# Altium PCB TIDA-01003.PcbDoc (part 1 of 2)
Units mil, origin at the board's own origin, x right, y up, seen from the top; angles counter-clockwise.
Board outline 1055.12 x 1877.5 mil, 6 copper layers (Layer 1 - Top Layer, Layer 2 - GND, Layer 3 - Signal, Layer 4 - Power, Layer 5 - GND, Layer 6 - Bottom Layer), stack 66.271 mil thick; 84 components, 50 nets, 343 pads, 124 vias.
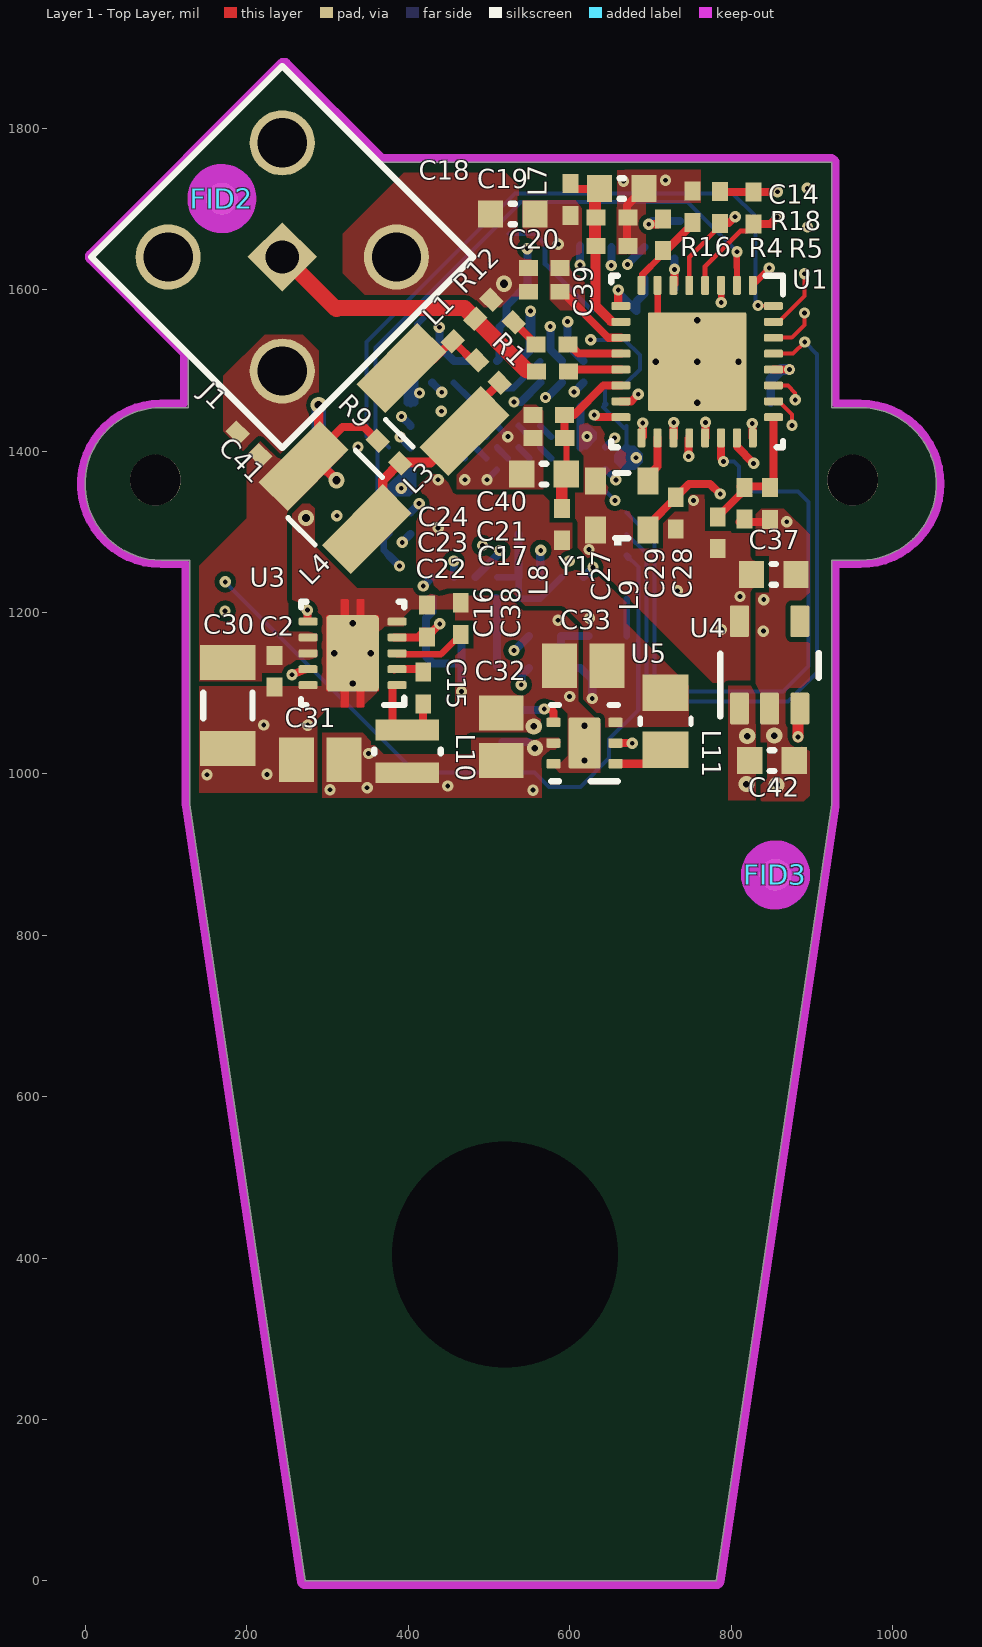
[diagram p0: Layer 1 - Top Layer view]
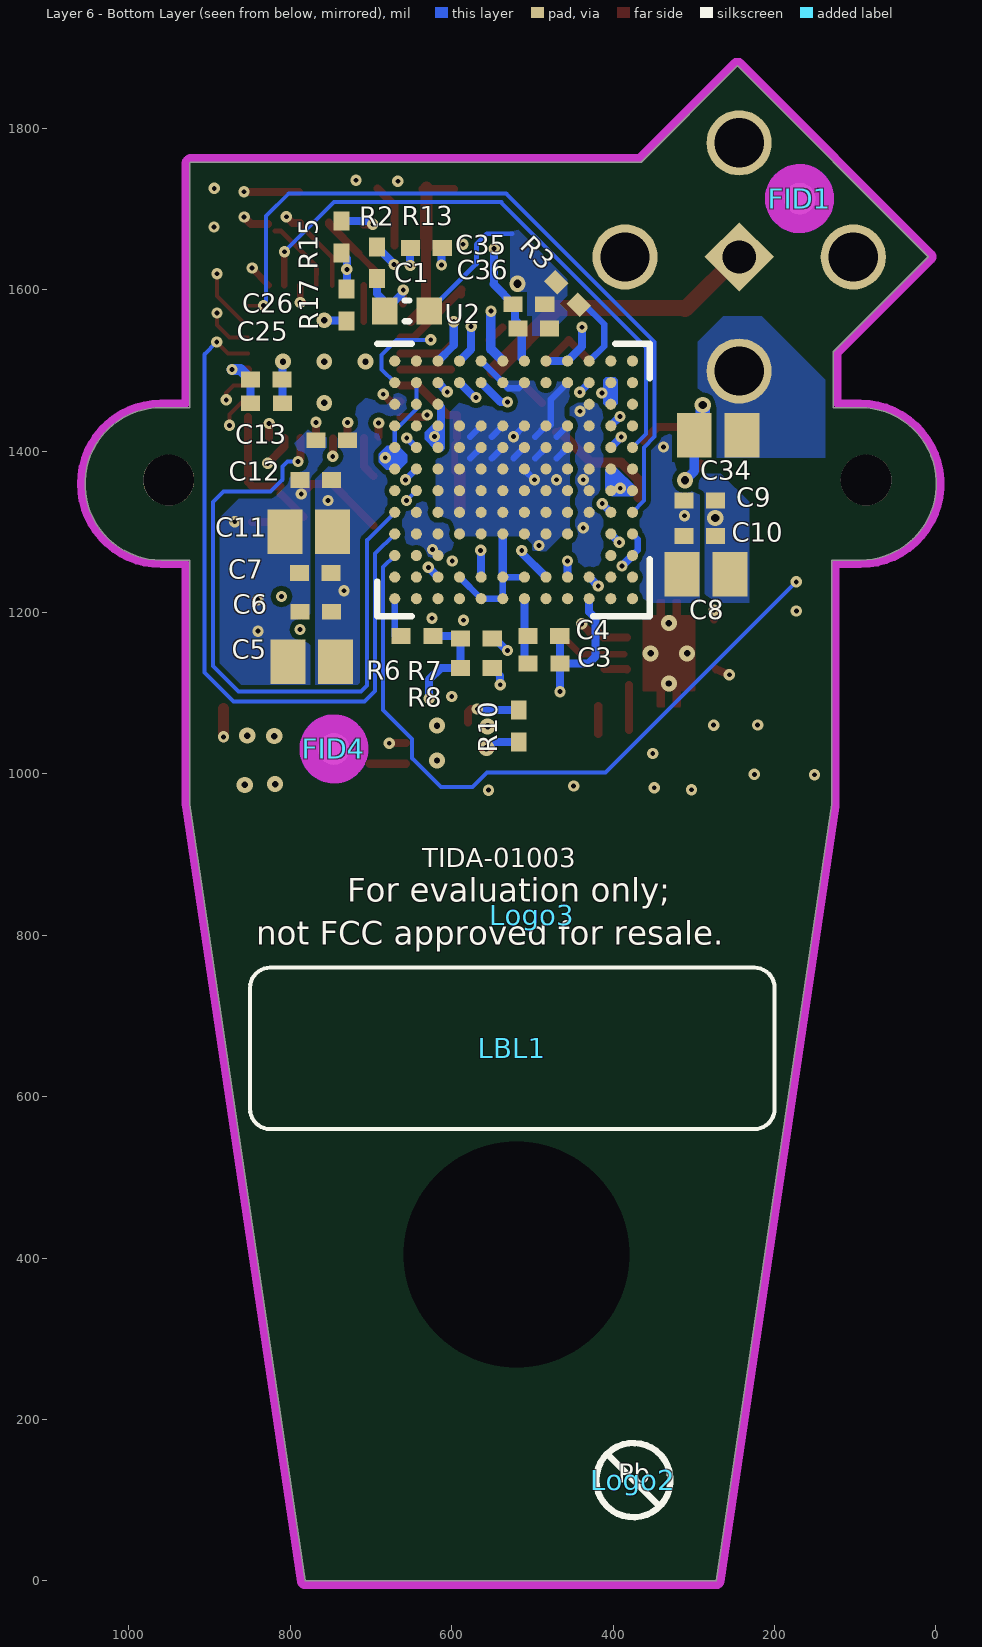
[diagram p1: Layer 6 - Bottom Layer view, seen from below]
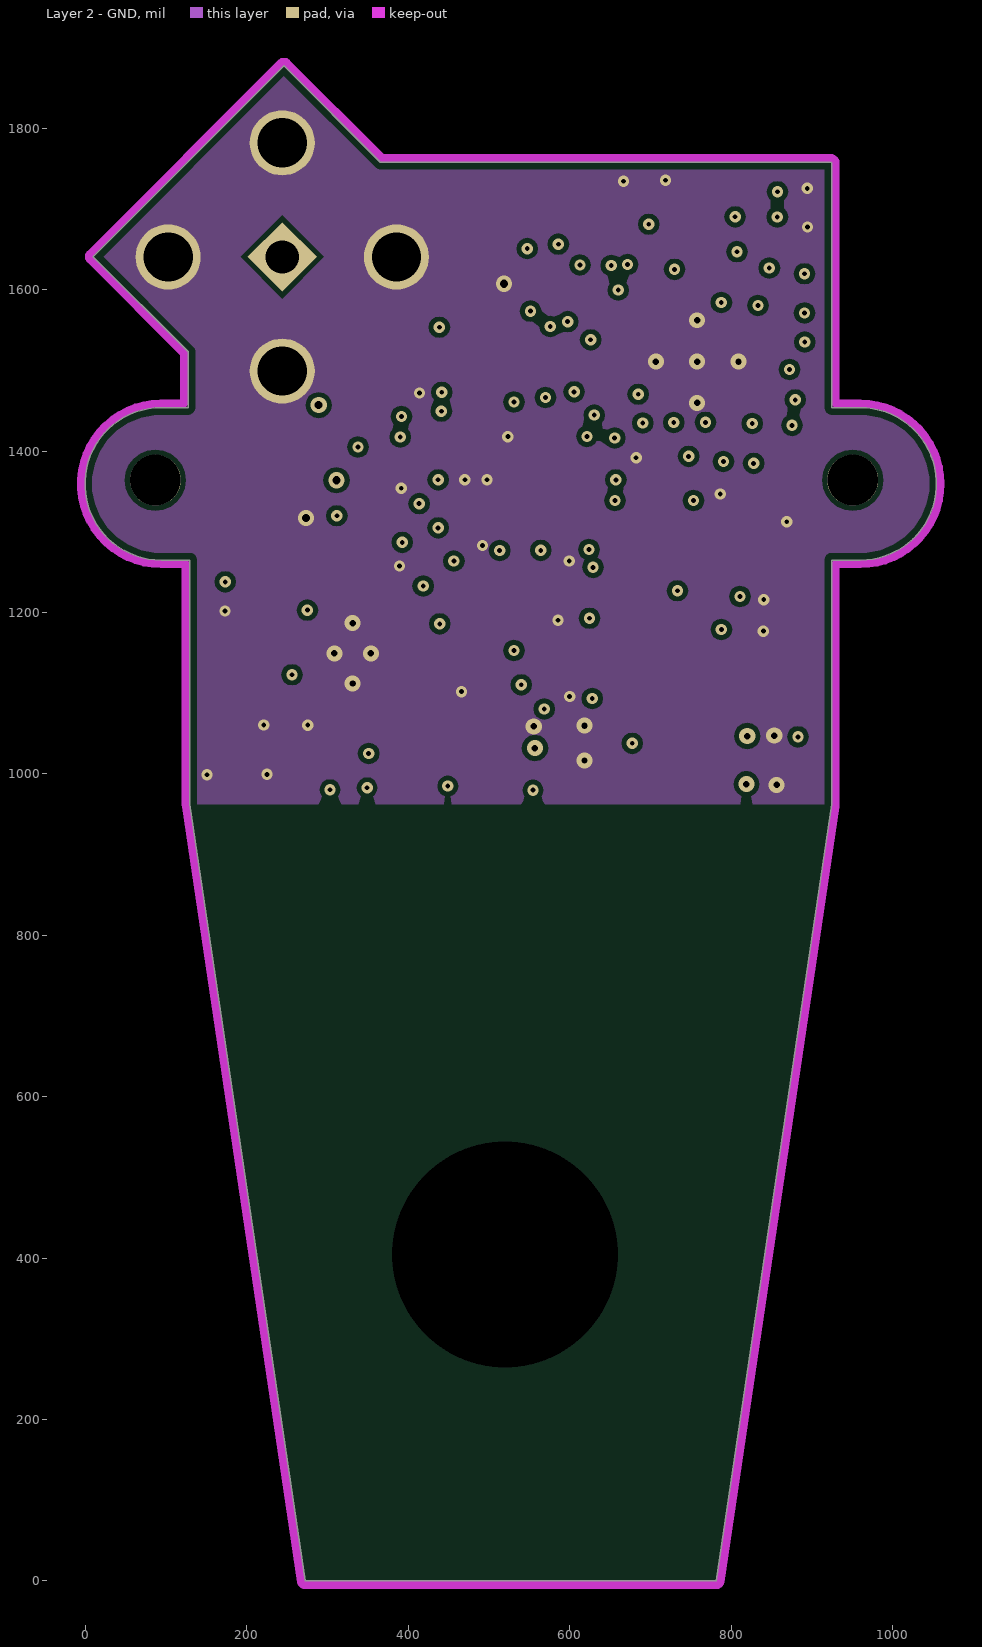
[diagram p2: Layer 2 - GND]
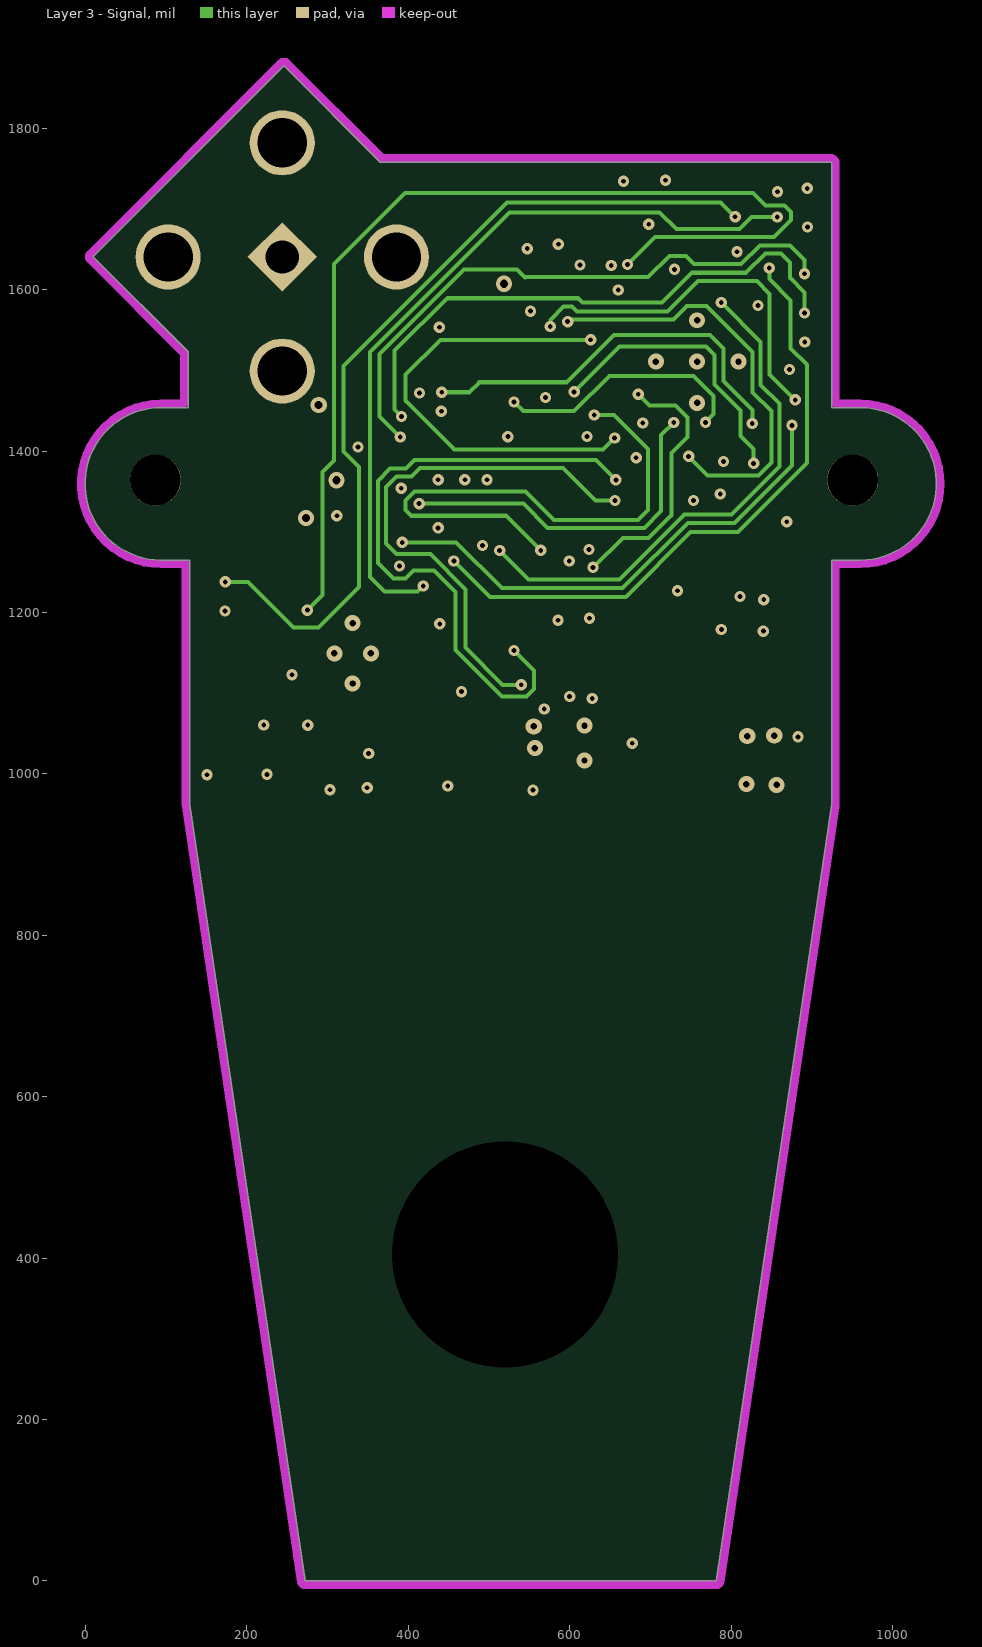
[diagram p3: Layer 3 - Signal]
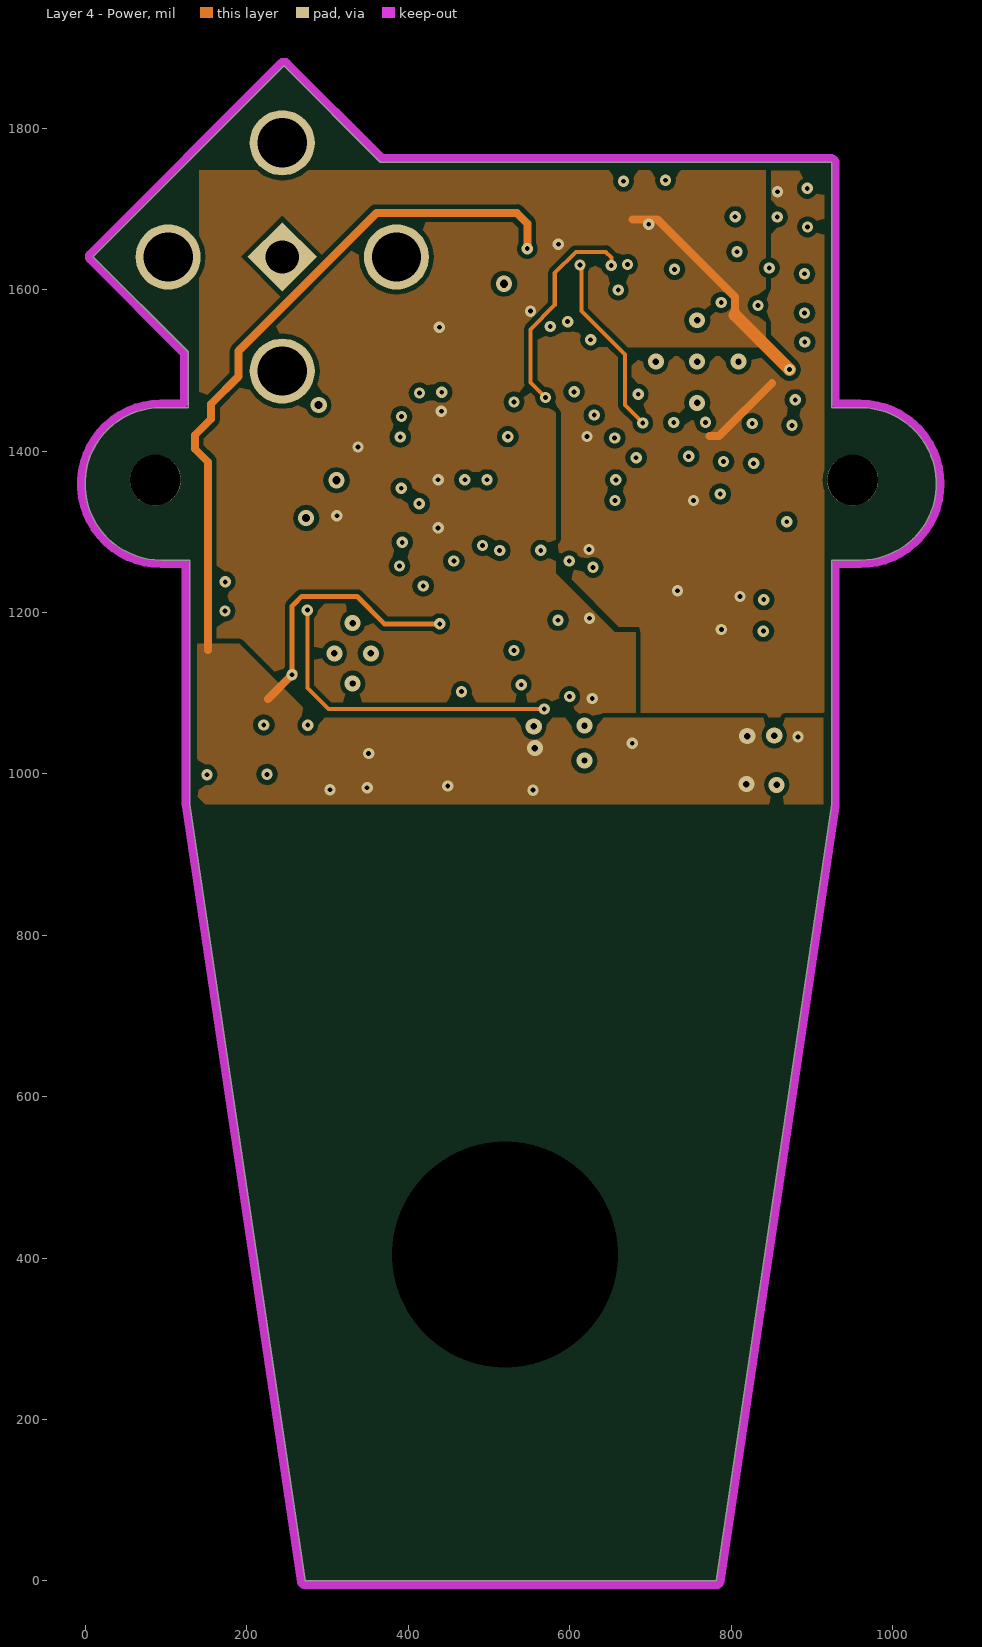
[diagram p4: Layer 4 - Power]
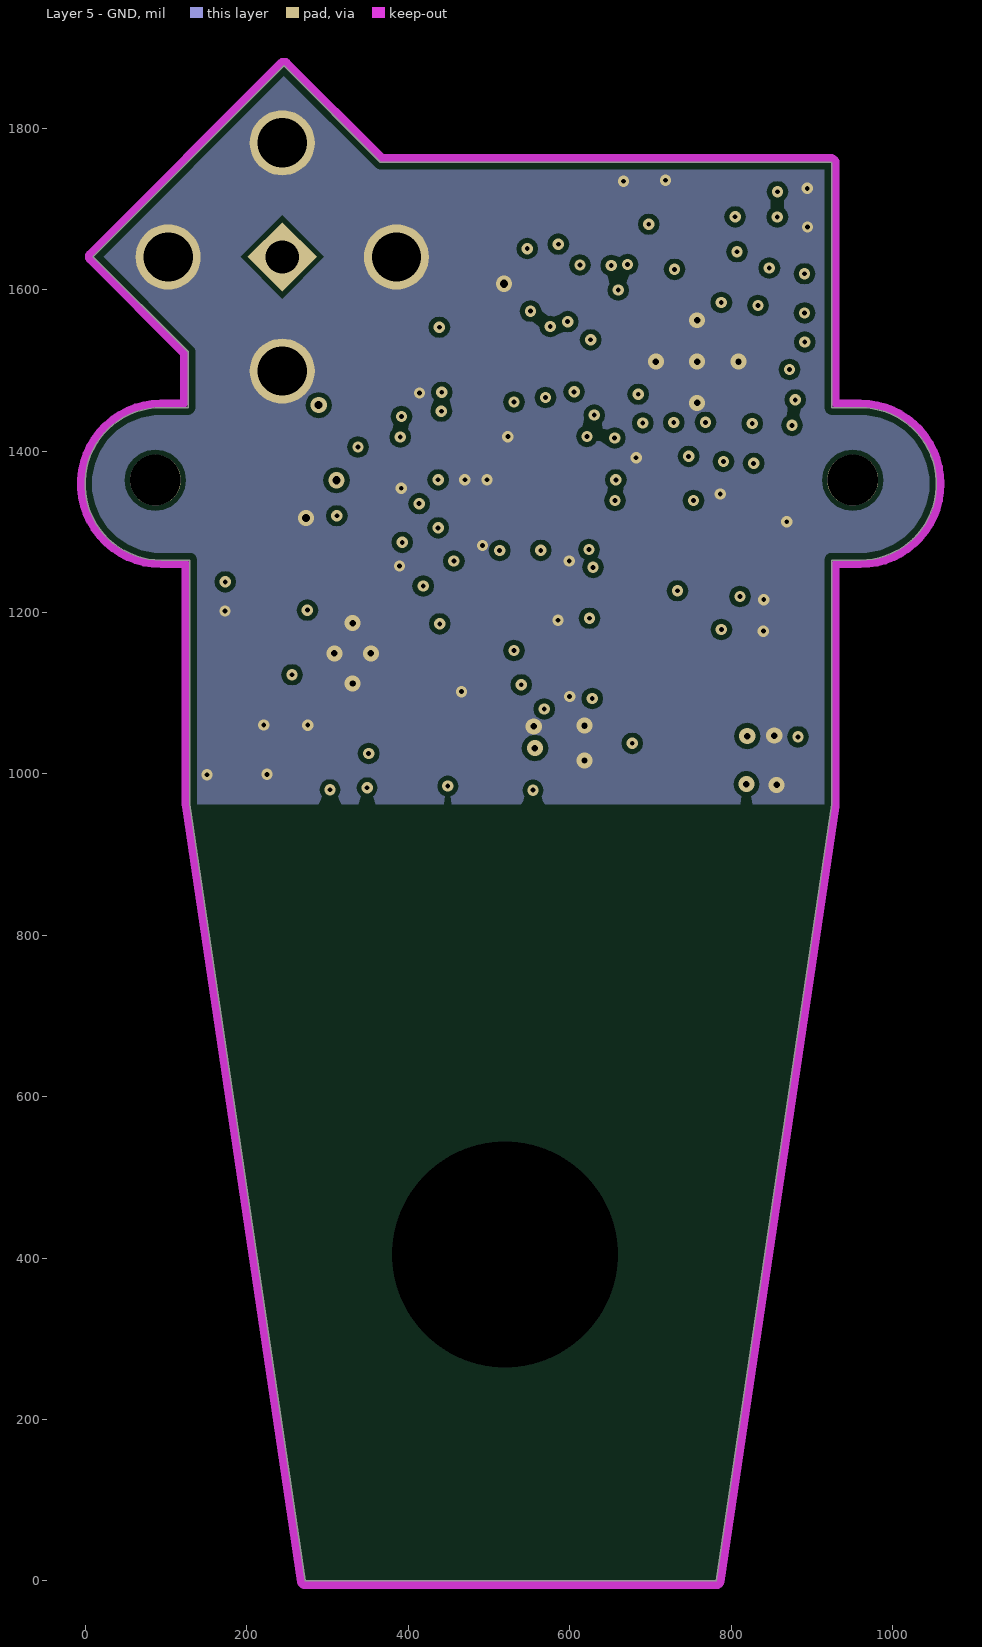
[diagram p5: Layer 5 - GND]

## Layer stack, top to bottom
Top Solder: solder mask 0.4, Solder Resist, Dk 3.5
Layer 1 - Top Layer: signal copper 1.4
Dielectric 1: core 12.6, 370HR, Dk 4.2
Layer 2 - GND: signal copper 1.417
Dielectric 2: prepreg 8, 370HR, Dk 4.2
Layer 3 - Signal: signal copper 1.417
Dielectric 3: core 16.6, 370HR, Dk 4.2
Layer 4 - Power: signal copper 1.417
Dielectric 4: prepreg 8, 370HR, Dk 4.2
Layer 5 - GND: signal copper 1.42
Dielectric 5: core 12.6, 370HR, Dk 4.2
Layer 6 - Bottom Layer: signal copper 1.4
Bottom Solder: solder mask 0.4, Solder Resist, Dk 3.5

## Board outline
93.88,1265.01 129.31,1265.01 129.31,961.86 129.31,962.5 272.2,0 781.7,0 924.59,962.5 924.59,961.86 924.59,1265.01 960.02,1265.01 ccw(c960.02,1359.5) 960.02,1453.99 924.59,1453.99 924.59,1757.14 923.6,1758.13 365.32,1758.13 245.95,1877.5 9.45,1641 127.32,1523.13 127.32,1453.99 93.88,1453.99 ccw(c93.88,1359.5)

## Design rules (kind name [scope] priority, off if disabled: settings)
AcuteAngle [All] p1: minimum=4.50000000000000E+0001 checktracksonly=FALSE
AssemblyTestPointUsage [All] p1: valid=2
BoardOutlineClearance BoardOutlineClearance_MountingHoles [OnCopper and InComponentClass('Mounting Holes')] p1: gap=40 ignorepadtopadclearanceinfootprint=FALSE
BoardOutlineClearance BoardOutlineClearance_Poly [OnCopper and InPoly] p2: gap=9 ignorepadtopadclearanceinfootprint=FALSE except(8.9: Arc-OutlineEdge Track-OutlineEdge SMDPad-OutlineEdge THPad-OutlineEdge Via-OutlineEdge Fill-OutlineEdge Poly-OutlineEdge Region-OutlineEdge Text-OutlineEdge)
BoardOutlineClearance [OnCopper and Not InComponentClass('Logo') and not InComponentClass('FiducialMark') and not InRegion(1000,500,4000,800)] p3: gap=9 ignorepadtopadclearanceinfootprint=FALSE
Clearance Clearance_fids [isarc or ispad vs iskeepout and HasFootprint('Fiducial10-20')] p1: gap=0 ignorepadtopadclearanceinfootprint=FALSE
Clearance Clearance_Keepouts [((IsTrack Or IsArc) And Not InPoly) And IsFree and IsKeepOut vs ((IsTrack Or IsArc) And Not InPoly) And IsFree and IsKeepOut] p2: gap=0 ignorepadtopadclearanceinfootprint=FALSE
Clearance Clearance_Poly [InPolygon] p3: gap=6 ignorepadtopadclearanceinfootprint=FALSE except(0: Arc-Hole Track-Hole SMDPad-Hole THPad-Hole Via-Hole Fill-Hole Poly-Hole Region-Hole Text-Hole)
Clearance [All] p4: gap=5 ignorepadtopadclearanceinfootprint=FALSE except(0: Arc-Hole Track-Hole SMDPad-Hole THPad-Hole Via-Hole Fill-Hole Poly-Hole Region-Hole Text-Hole)
ComponentClearance ComponentClearance_MountingHoles_FiducialMarks [InComponentClass('Mounting Holes') vs InComponentClass('FiducialMark')] p1: gap=5 collisioncheckmode=3 verticalgap=10 showdistances=FALSE
ComponentClearance ComponentClearance_J1_SHUNT1 [InComponent('J1') vs InComponent('FID2')] p2: gap=0 collisioncheckmode=3 verticalgap=0 showdistances=FALSE
ComponentClearance ComponentClearance_Logo [InComponentClass('Logo')] p3: gap=5 collisioncheckmode=3 verticalgap=5 showdistances=FALSE
ComponentClearance ComponentClearance_ScrewToNut [(HasFootprint('NY PMS 440 0025 PH')) vs (HasFootprint('Keystone_1902C'))] p4: gap=5 collisioncheckmode=3 verticalgap=10 showdistances=FALSE
ComponentClearance ComponentClearance_MountingHoles [InComponentClass('Mounting Holes')] p5: gap=5 collisioncheckmode=3 verticalgap=100000 showdistances=FALSE
ComponentClearance ComponentClearance_SmallPassives [HasFootprint('0201*') or HasFootprint('0402*') or HasFootprint('0508') or HasFootprint('0603*') or HasFootprint('0612') or HasFootprint('0805*') or HasFootprint('0815*') or HasFootprint('0830*') or HasFootprint('1206*') or HasFootprint('1210*') or HasFootprint('1808*') or HasFootprint('1812*') or HasFootprint('1825*') or HasFootprint('2010*') or HasFootprint('2220*') or HasFootprint('2225*') or HasFootprint('2512*') or HasFootprint('2728*') or HasFootprint('3518*') vs HasFootprint('0201*') or HasFootprint('0402*') or HasFootprint('0508') or HasFootprint('0603*') or HasFootprint('0612') or HasFootprint('0805*') or HasFootprint('0815*') or HasFootprint('0830*') or HasFootprint('1206*') or HasFootprint('1210*') or HasFootprint('1808*') or HasFootprint('1812*') or HasFootprint('1825*') or HasFootprint('2010*') or HasFootprint('2220*') or HasFootprint('2225*') or HasFootprint('2512*') or HasFootprint('2728*') or HasFootprint('3518*')] p6: gap=5 collisioncheckmode=3 verticalgap=10 showdistances=FALSE
ComponentClearance ComponentClearance_THtoSMT [IsThruComponent vs IsSMTComponent] p7: gap=5 collisioncheckmode=3 verticalgap=30 showdistances=FALSE
ComponentClearance ComponentClearance_THtoTH [IsThruComponent vs IsThruComponent] p8: gap=5 collisioncheckmode=3 verticalgap=30 showdistances=FALSE
ComponentClearance [All] p9: gap=5 collisioncheckmode=3 verticalgap=10 showdistances=FALSE
DiffPairsRouting [All] p1: maxlimit=100 minlimit=10 mostfreqgap=10 toplayer_minwidth=15 toplayer_maxwidth=15 toplayer_prefwidth=15 midlayer1_minwidth=15 midlayer1_maxwidth=15 midlayer1_prefwidth=15 midlayer2_minwidth=15 midlayer2_maxwidth=15 midlayer2_prefwidth=15 midlayer3_minwidth=15 midlayer3_maxwidth=15 midlayer3_prefwidth=15 midlayer4_minwidth=15 midlayer4_maxwidth=15 midlayer4_prefwidth=15 bottomlayer_minwidth=15 bottomlayer_maxwidth=15 bottomlayer_prefwidth=15 maxuncoupledlength=1000
FabricationTestPointUsage TestPointUsage [All] p1: valid=2 allowmultiple=FALSE
FabricationTestpoint Testpoint [All] p1: side=3 testpointundercomponent=TRUE minsize=40 maxsize=100 preferedsize=60 minholesize=0 maxholesize=40 preferedholesize=32 testpointgrid=1 allowsidetop=TRUE allowsidebottom=TRUE usegrid=TRUE gridtolerance=0.01
FanoutControl Fanout_LCC [IsLCC] p1: bgadir=Out bgaviamode=Centered fanoutstyle=Auto fanoutdirection=Alternating viagrid=1 // Fanout_LCC (Default Rule)
FanoutControl Fanout_BGA [IsBGA] p2: bgadir=Out bgaviamode=Centered fanoutstyle=Auto fanoutdirection=Alternating viagrid=1 // Fanout_BGA (Default Rule)
FanoutControl Fanout_Default [All] p4: bgadir=Out bgaviamode=Centered fanoutstyle=Auto fanoutdirection=Alternating viagrid=1 // Fanout_Default (Default Rule)
FanoutControl Fanout_Small [(CompPinCount < 5)] p5: bgadir=Out bgaviamode=Centered fanoutstyle=Auto fanoutdirection=OutThenIn viagrid=1 // Fanout_Small (Default Rule)
HoleSize [All] p1: absolutevalues=TRUE maxlimit=281 minlimit=6 maxpercent=80.000 minpercent=20.000
MinimumAnnularRing MinimumAnnularRing_ThermalPadVias [IsVia and InAnyComponent] p1: minimumring=5.91
MinimumAnnularRing [All] p2: minimumring=4
MinimumSolderMaskSliver MinimumSolderMaskSliver_Logo [InComponentClass('Logo') vs InComponentClass('Logo')] p1: minsoldermaskwidth=0.7
MinimumSolderMaskSliver [All] p2: minsoldermaskwidth=3
PlaneConnect [All] p1: planeconnectstyle=Relief reliefexpansion=10 reliefentries=4 reliefconductorwidth=10 reliefairgap=10
PolygonConnect [All] p1: connectstyle=Direct reliefconductorwidth=10 reliefentries=4 polygonreliefangle="90 Angle" airgapwidth=10
RoutingVias ThermalPadVias [IsVia and InAnyComponent] p1: holewidth=7.87 width=19.68 viastyle="Through Hole" minholewidth=7.87 minwidth=19.68 maxholewidth=12.99 maxwidth=23.62
RoutingVias [All] p2: holewidth=16 width=34 viastyle="Through Hole" minholewidth=6 minwidth=14 maxholewidth=40 maxwidth=65
SilkToBoardRegionClearance [Not ((IsComment or IsDesignator) And (Hide <> 'False')) and not InRegion(1000,500,4000,800)] p1:
SilkToSilkClearance SilkToSilkClearance_Pb-FreeLogo [(HasFootprint('Pb-Free_Overlay_Medium') OR HasFootprint('Pb-Free_Overlay_Small')) vs (HasFootprint('Pb-Free_Overlay_Medium') OR HasFootprint('Pb-Free_Overlay_Small'))] p1: silktosilkclearance=0
SilkToSilkClearance [All] p2: silktosilkclearance=4
SilkToSolderMaskClearance SilkToComponentPadClearance [IsPad and InAnycomponent] p1: minsilkscreentomaskgap=3 clearancetoexposedcopper=TRUE
SilkToSolderMaskClearance "Silk to Solder Mask Opening" [All] p2: minsilkscreentomaskgap=3 clearancetoexposedcopper=FALSE
SolderMaskExpansion [All] p1: expansion=1.97
Width [All] p1: maxlimit=100 minlimit=5 preferedwidth=10 minimp=50.000000 maximp=50.000000 favimp=50.000000 checkconnectedcopper=TRUE
15 further rules are at their usual default settings.

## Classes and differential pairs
component class "Wide Vin Serializer": C1 C14 C17 C18 C19 C20 C21 C22 C23 C24 C25 C26 C27 C28 C29 C39 C40 L7 L8 L9 R2 R12 R13 R15 R16 R17 R18 U1 Y1
component class "Wide Vin Power Supply and PoC Filter": C2 C15 C16 C30 C31 C32 C33 C34 C37 C38 C41 C42 J1 L1 L3 L4 L10 L11 R1 R9 R10 U3 U4 U5
component class "Wide Vin ON Semi Imager + Processor": C3 C4 C5 C6 C7 C8 C9 C10 C11 C12 C13 C35 C36 R3 R4 R5 R6 R7 R8 U2
component class TIDA-01003_EVM_Hardware: FID1 FID2 FID3 FID4 LBL1 Logo2 Logo3 ZZ1 ZZ2 ZZ3 ZZ4
component class FiducialMark: FID1 FID2 FID3 FID4
component class AssemblyNote: ZZ1 ZZ2 ZZ3 ZZ4
component class Label: LBL1

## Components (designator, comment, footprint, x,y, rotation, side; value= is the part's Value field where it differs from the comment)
C1 "C1608X7R1H474K080AC" 0603L 655.4,1573.9 r180 bottom value=0.47uF
C2 "CGA2B3X7R1H104K050BB" 0402L 234.1,1127.3 r270 top value=0.1uF
C3 "GRM155R61A105KE15D" 0402L 485.8,1136.9 r180 bottom value=1uF
C4 "GRM155R71C104KA88D" 0402L 485.9,1170.8 r180 bottom value=0.1uF
C5 "GRM21BR71A106KE51L" 0805L 773.5,1139 r0 bottom value=10uF
C6 "GCM155R71C104KA55D" 0402L 768.63,1201.06 r0 bottom value=0.1uF
C7 "GRM155R71C103KA01D" 0402L 769.1,1249.16 r0 bottom value=0.01uF
C8 "GRM21BR71A106KE51L" 0805L 285,1247.5 r180 bottom value=10uF
C9 "GCM155R71C104KA55D" 0402L 292.8,1338.7 r180 bottom value=0.1uF
C10 "GRM155R71C103KA01D" 0402L 292.8,1294.71 r180 bottom value=0.01uF
C11 "GRM21BR71A106KE51L" 0805L 777.13,1300.16 r0 bottom value=10uF
C12 "GRM155R61A105KE15D" 0402L 768.5,1364.5 r0 bottom value=1uF
C13 "GRM155R71C103KA01D" 0402L 748.7,1413.6 r0 bottom value=0.01uF
C14 "JMK107BB7475MA-T" 0603L 664.5,1725.5 r0 top value=4.7uF
C15 "GRM155R71C104KA88D" 0402L 418.5,1106.5 r270 top value=0.1uF
C16 "GRM155R71C103KA01D" 0402L 423,1189.5 r90 top value=0.01uF
C17 "CGA2B3X7R1H104K050BB" 0402L 578.66,1498.51 r0 top value=0.1uF
C18 "CL10B475KQ8NQNC" 0603L 529.5,1694 r180 top value=4.7µF
C19 "GRM155R71C104KA88D" 0402L 568.5,1627 r180 top value=0.1uF
C20 "GRM155R71C103KA01D" 0402L 568.5,1597.5 r180 top value=0.01uF
C21 "CGA2B3X7R1H473K050BB" 0402L 578,1532 r0 top value=0.047uF
C22 "CL10B475KQ8NQNC" 0603L 568,1371.5 r180 top value=4.7µF
C23 "GRM155R71C104KA88D" 0402L 574.2,1416.4 r180 top value=0.1uF
C24 "GRM155R71C103KA01D" 0402L 574,1445 r180 top value=0.01uF
C25 "GRM155R71C104KA88D" 0402L 829.5,1459.45 r180 bottom value=0.1uF
C26 "GRM155R71C103KA01D" 0402L 829.8,1488.85 r180 bottom value=0.01uF
C27 "GRM155R71C104KA88D" 0402L 731.5,1323.2 r90 top value=0.1uF
C28 "GRM155R71C104KA88D" 0402L 848,1335.2 r270 top value=0.1uF
C29 "GRM155R71C103KA01D" 0402L 816.5,1335.5 r270 top value=0.01uF
C30 "CGA5L3X5R1H106K160AB" 1206_190L 176.5,1085 r270 top value=10uF
C31 "CL21B226MQQNNNE" 0805L 291,1017.5 r180 top value=22uF
C32 "CL21B106KOQNNNE" 0805L 515.5,1046 r90 top value=10uF
C33 "GRM21BR71A106KE51L" 0805L 616.8,1134.3 r180 top value=10uF
C34 "CGA4J3X5R1H475M125AB" 0805L 270,1420 r180 bottom value=4.7uF
C35 "GRM155R61A105KE15D" 0402L 504.5,1582 r180 bottom value=1uF
C36 "C1005X7R1E104K050BB" 0402L 498.5,1552 r180 bottom value=0.1µF
C37 "LMK107B7105KAHT" 0603L 852.9,1247.41 r0 top value=1uF
C38 "GRM155R61A105KE15D" 0402L 465,1192.5 r90 top value=1uF
C39 "GRM155R71C104KA88D" 0402L 652.5,1689.4 r0 top value=0.1uF
C40 "GRM155R71C103KA01D" 0402L 652.5,1654 r0 top value=0.01uF
C41 "CGA2B3X7R1H104K050BB" 0402L 202.42,1409.08 r135 top value=0.1uF
C42 "LMK107B7105KAHT" 0603L 850.5,1016.5 r0 top value=1uF
FID1 "Fiducial" Fiducial10-20 169,1713 r180 bottom
FID2 "Fiducial" Fiducial10-20 169,1713 r0 top
FID3 "Fiducial" Fiducial10-20 855,875 r0 top
FID4 "Fiducial" Fiducial10-20 746,1031 r180 bottom
J1 "59S10H-40ML5-Z" Rosenberger_59S10H-40ML5-Z 243.88,1640.63 r225 top
L1 "BLM15AX102SN1D" 0402L 469,1550 r225 top value="1000 ohm"
L3 "CBC3225T4R7MR" CBC3225 430.5,1464 r315 top value=4.7uH
L4 "CBC3225T101MR" CBC3225 309.5,1342.5 r135 top value=100uH
L7 "BLM15AX102SN1D" 0402L 600.9,1711.9 r90 top value="1000 ohm"
L8 "BLM15AX102SN1D" 0402L 590.3,1309.3 r90 top value="1000 ohm"
L9 "BLM15AX102SN1D" 0402L 783.5,1299 r90 top value="1000 ohm"
L10 "NRV2010T4R7MGF" NRV2010 399,1028 r270 top value=4.7uH
L11 "MLZ2012M2R2HTD25" 0805_150 718.8,1065.3 r90 top value=2.2uH
LBL1 "Size: 0.65\" x 0.20 \"" Label_650x200 525,660 r0 bottom
Logo2 "Pb-Free Symbol" Pb-Free_Overlay_Small 375,125 r180 bottom
Logo3 "FCC disclaimer" FCC_disclaimer_stacked 500,825 r180 bottom
R1 "CRCW04022K00FKED" 0402L 499.5,1498.5 r135 top value=2.00k
R2 "CRCW040210K0JNED" 0402L 692.8,1633.5 r90 bottom value=10k
R3 "CRCW040210K0JNED" 0402L 456.5,1595.5 r225 bottom value=10k
R4 "CRCW04023K30JNED" 0402L 786.5,1702 r90 top value=3.3k
R5 "CRCW04023K30JNED" 0402L 827.6,1701.2 r90 top value=3.3k
R6 "CRCW040210K0JNED" 0402L 643,1171 r180 bottom value=10k
R7 "CRCW04023K30JNED" 0402L 569.5,1168 r0 bottom value=3.3k
R8 "CRCW04023K30JNED" 0402L 569.5,1131.5 r0 bottom value=3.3k
R9 "CRCW04022K00FKED" 0402L 376,1399 r315 top value=2.00k
R10 "CRCW04021K00FKED" 0402L 517,1059.5 r270 bottom value=1.00k
R12 "CRCW040249R9FKED" 0402L 517,1573.5 r135 top value=49.9
R13 "CRCW040233R0JNED" 0402L 631.5,1651.7 r0 bottom value=33
R15 "CRCW040210K0JNED" 0402L 736.6,1665.3 r90 bottom value=10k
R16 "CRCW040210K0JNED" 0402L 715.8,1668.2 r90 top value=10k
R17 "CRCW04020000Z0ED" 0402L 730.3,1581.2 r90 bottom value=0
R18 "CRG0402F4K7" 0402L 752.3,1702.8 r270 top value=4.70k
U1 "DS90UB913ATRTVTQ1" RTV0032A 758,1511 r270 top
U2 "ON Semiconductor AS0140AT" BGA130_850x850x162 523.4,1364.43 r0 bottom locked
U3 "LM53600NQDSXRQ1" DSX0010A 331,1149.5 r180 top
U4 "LP5907QMFX-2.8Q1" DBV0005A_N 847.8,1135.21 r90 top
U5 "TPS62261TDRVRQ1" DRV0006A 618.3,1038.3 r180 top
Y1 "ASDMB-48.000MHZ-LY-T" Abracon_ASDMB 664.5,1332.6 r90 top
ZZ1 "This Assembly Note is for PCB labels only" AssemblyNoteLabel 185,3938 r0 top
ZZ2 "These assemblies are ESD sensitive, ESD precautions shall be observed." AssemblyNote 185,3829.11 r0 top
ZZ3 "These assemblies must be clean and free from flux and all contaminants. Use of no clean flux is not acceptable." AssemblyNote 185,3740.56 r0 top
ZZ4 "These assemblies must comply with workmanship standards IPC-A-610 Class 2, unless otherwise specified." AssemblyNote 185,3652 r0 top

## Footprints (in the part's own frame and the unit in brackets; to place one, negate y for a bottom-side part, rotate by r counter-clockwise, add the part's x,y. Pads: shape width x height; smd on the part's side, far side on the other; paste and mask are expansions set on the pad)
0402L [mm] "0402 from SM-752 data"
  rect 0.6x0.5 smd: 1(-0.5,0) 2(0.5,0)
  body extent -0.55,-0.3 0.55,0.3, height 0.6
0603L [mm] "0603 from SM-752 data"
  rect 0.8x0.85 smd: 1(-0.7,0) 2(0.7,0)
  silkscreen extent -0.07,-0.33 0.07,0.33, body extent -0.87,-0.47 0.87,0.47, height 1
0805_150 [mm] "0805 / 1.5 mm height"
  rect 1.15x1.45 smd: 1(-0.9,0) 2(0.9,0)
  silkscreen extent -0.1,-0.8 0.1,0.8, body extent -1.1,-0.72 1.1,0.72, height 1.5
0805L [mm] "0805 from SM-752 data"
  rect 1.1x1.4 smd: 1(-0.75,0) 2(0.75,0)
  body extent -1.1,-0.72 1.1,0.72, height 1.45
1206_190L [mm] "1206_190"
  rect 1.1x1.75 smd: 1(-1.35,0) 2(1.35,0)
  silkscreen extent -0.4,-0.77 0.4,0.77, body extent -1.75,-0.95 1.75,0.95, height 1.9
Abracon_ASDMB [mm] "SMD, 4-Leads, Body 2.5x2mm"
  rect 0.85x0.65 smd: 1(-0.775,0.825) 2(-0.775,-0.825) 3(0.775,-0.825) 4(0.775,0.825)
  silkscreen extent -1.25,-0.2 1.02,0.25, body extent -1.02,-1.27 1.02,1.28, height 0.91
AssemblyNote [mil] "Assembly Note"
AssemblyNoteLabel [mil] "Assembly Note for PCB Labels"
BGA130_850x850x162 [mm] "BGA, 130-Balls, Body 8.5x8.5mmx1.62mm, Pitch 0.68mm"
  round 0.35 smd: A1(-3.74,3.74) A2(-3.06,3.74) A3(-2.38,3.74) A4(-1.7,3.74) A5(-1.02,3.74) A6(-0.34,3.74) A7(0.34,3.74) A8(1.02,3.74) A9(1.7,3.74) A10(2.38,3.74) A11(3.06,3.74) A12(3.74,3.74) B1(-3.74,3.06) B2(-3.06,3.06) B3(-2.38,3.06) B4(-1.7,3.06) B5(-1.02,3.06) B6(-0.34,3.06) B7(0.34,3.06) B8(1.02,3.06) B9(1.7,3.06) B10(2.38,3.06) B11(3.06,3.06) B12(3.74,3.06) C1(-3.74,2.38) C2(-3.06,2.38) C10(2.38,2.38) C11(3.06,2.38) C12(3.74,2.38) D1(-3.74,1.7) D2(-3.06,1.7) D4(-1.7,1.7) D5(-1.02,1.7) D6(-0.34,1.7) D7(0.34,1.7) D8(1.02,1.7) D9(1.7,1.7) D10(2.38,1.7) D11(3.06,1.7) D12(3.74,1.7) E1(-3.74,1.02) E2(-3.06,1.02) E3(-2.38,1.02) E4(-1.7,1.02) E5(-1.02,1.02) E6(-0.34,1.02) E7(0.34,1.02) E8(1.02,1.02) E9(1.7,1.02) E10(2.38,1.02) E11(3.06,1.02) E12(3.74,1.02) F1(-3.74,0.34) F2(-3.06,0.34) F3(-2.38,0.34) F4(-1.7,0.34) F5(-1.02,0.34) F6(-0.34,0.34) F7(0.34,0.34) F8(1.02,0.34) F9(1.7,0.34) F10(2.38,0.34) F11(3.06,0.34) F12(3.74,0.34) G1(-3.74,-0.34) G2(-3.06,-0.34) G3(-2.38,-0.34) G4(-1.7,-0.34) G5(-1.02,-0.34) G6(-0.34,-0.34) G7(0.34,-0.34) G8(1.02,-0.34) G9(1.7,-0.34) G10(2.38,-0.34) G11(3.06,-0.34) G12(3.74,-0.34) H1(-3.74,-1.02) H2(-3.06,-1.02) H3(-2.38,-1.02) H4(-1.7,-1.02) H5(-1.02,-1.02) H6(-0.34,-1.02) H7(0.34,-1.02) H8(1.02,-1.02) H9(1.7,-1.02) H10(2.38,-1.02) H11(3.06,-1.02) H12(3.74,-1.02) J1(-3.74,-1.7) J2(-3.06,-1.7) J3(-2.38,-1.7) J4(-1.7,-1.7) J5(-1.02,-1.7) J6(-0.34,-1.7) J7(0.34,-1.7) J8(1.02,-1.7) J9(1.7,-1.7) J10(2.38,-1.7) J11(3.06,-1.7) J12(3.74,-1.7) K1(-3.74,-2.38) K2(-3.06,-2.38) K3(-2.38,-2.38) K10(2.38,-2.38) K11(3.06,-2.38) K12(3.74,-2.38) L1(-3.74,-3.06) L2(-3.06,-3.06) L3(-2.38,-3.06) L4(-1.7,-3.06) L5(-1.02,-3.06) L6(-0.34,-3.06) L7(0.34,-3.06) L8(1.02,-3.06) L9(1.7,-3.06) L10(2.38,-3.06) L11(3.06,-3.06) L12(3.74,-3.06) M1(-3.74,-3.74) M2(-3.06,-3.74) M3(-2.38,-3.74) M4(-1.7,-3.74) M5(-1.02,-3.74) M6(-0.34,-3.74) M7(0.34,-3.74) M8(1.02,-3.74) M9(1.7,-3.74) M10(2.38,-3.74) M11(3.06,-3.74) M12(3.74,-3.74)
  silkscreen extent -4.29,-4.29 4.29,4.29, body extent -4.34,-4.34 4.34,4.34, height 1.62
CBC3225 [mm] "TAIYO YUDEN, IPC nominal footprint."
  rect 1.29x2.72 smd: 1(-1.405,0) 2(1.405,0)
  silkscreen extent -0.6,-1.5 0.6,-1.5, body extent -1.7,-1.35 1.7,1.35, height 2.7
DBV0005A_N [mm] "SOT23, 5-Leads, Body 2.9x1.6mm, Pitch 0.95mm, Lead Span 2.8mm, IPC Medium Density"
  rrect17% 1x0.6 smd: 1(-1.375,0.95) 2(-1.375,0) 3(-1.375,-0.95) 4(1.375,-0.95) 5(1.375,0.95)
  silkscreen extent -1.63,-1.55 0.38,1.55, body extent -1.42,-1.46 1.42,1.46, height 1.09
DRV0006A [mm] "SON, 6-Leads, Body 2x2mm, Pitch 0.65mm, Thermal Pad 1.6x1mm, TI Recommended"
  rrect33% 0.45x0.3 smd: 1(-0.975,0.65) 2(-0.975,0) 3(-0.975,-0.65) 4(0.975,-0.65) 5(0.975,0) 6(0.975,0.65)
  rrect14% 1x0.7 on Top Paste: 7(0,0.45) 7(0,-0.45)
  rrect10% 1x1.6 smd paste-0.5: 7(0,0)
  silkscreen extent -1.05,-1.2 1.05,1.2, body extent -1.05,-1.05 1.05,1.05, height 0.81
DSX0010A [mm] "SON, 10-Leads, Body 3x3 mm, Pitch 0.5mm"
  rrect40% 0.6x0.25 smd: 1(-1.4,1) 2(-1.4,0.5) 3(-1.4,0) 4(-1.4,-0.5) 5(-1.4,-1) 6(1.4,-1) 7(1.4,-0.5) 8(1.4,0) 9(1.4,0.5) 10(1.4,1)
  rrect40% 0.25x0.34 on Top Paste: 11(-0.25,1.53) 11(-0.25,-1.53) 11(0.25,1.53) 11(0.25,-1.53)
  rrect9% 1.5x1.06 on Top Paste: 11(0,0.63) 11(0,-0.63)
  rrect12% 1.65x2.4 smd paste-1 mask-2: 11(0,0)
  Layer 1 - Top Layer region: -0.775,-1.2 -0.375,-1.2 -0.375,-1.65 -0.371,-1.669 -0.36,-1.685 -0.344,-1.696 -0.325,-1.7 -0.325,-1.7 -0.325,-1.7 -0.175,-1.7 -0.175,-1.7 -0.156,-1.696 -0.14,-1.685 -0.129,-1.669 -0.125,-1.65 -0.125,-1.65 -0.125,-1.65 -0.125,-1.2 0.125,-1.2 0.125,-1.65 0.129,-1.669 0.14,-1.685 0.156,-1.696 0.175,-1.7 0.175,-1.7 0.175,-1.7 0.325,-1.7 0.325,-1.7 0.344,-1.696 0.36,-1.685 0.371,-1.669 0.375,-1.65 0.375,-1.65 0.375,-1.2 0.775,-1.2 0.794,-1.196 0.81,-1.185 0.821,-1.169 0.825,-1.15 0.825,-1.15 0.825,1.15 0.821,1.169 0.81,1.185 0.794,1.196 0.775,1.2 0.775,1.2 0.375,1.2 0.375,1.65 0.371,1.669 0.36,1.685 0.344,1.696 0.325,1.7 0.325,1.7 0.175,1.7 0.156,1.696 0.14,1.685 0.129,1.669 0.125,1.65 0.125,1.65 0.125,1.2 -0.125,1.2 -0.125,1.65 -0.125,1.65 -0.129,1.669 -0.14,1.685 -0.156,1.696 -0.175,1.7 -0.175,1.7 -0.325,1.7 -0.344,1.696 -0.36,1.685 -0.371,1.669 -0.375,1.65 -0.375,1.65 -0.375,1.2 -0.775,1.2 -0.794,1.196 -0.81,1.185 -0.821,1.169 -0.825,1.15 -0.825,1.15 -0.825,-1.15 -0.821,-1.169 -0.81,-1.185 -0.794,-1.196 -0.775,-1.2
  silkscreen extent -1.63,-1.63 1.63,1.63, body extent -1.5,-1.5 1.5,1.5, height 0.8
FCC_disclaimer_stacked [mil]
Fiducial10-20 [mm]
  round 1 smd mask+0.5: 1(0,0)
  Layer 1 - Top Layer keep-out circle w1.178: c0,0 r0.5
Label_650x200 [mil] "Thermal Transfer Label"
  round 1 on Mech14: 0(0,0)
  silkscreen extent -325,-100 325,100, body extent -325,-100 325,100, height 1
NRV2010 [mm] "SMD, 2-Leads, Body 2x2mm"
  rect 0.65x2 smd: 1(-0.675,0) 2(0.675,0)
  silkscreen extent -0.06,-1.05 0.06,1.05, body extent -1.05,-1.05 1.05,1.05, height 1
Pb-Free_Overlay_Small [mil]
  silkscreen extent -46,-46 46,46
Rosenberger_59S10H-40ML5-Z [mm] "Connector, HF, TH"
  rect 1.55x1.55 hole 1.05: 1(0,0)
  round 2.05 hole 1.55: 2(-2.54,2.54) 3(2.54,2.54) 4(2.54,-2.54) 5(-2.54,-2.54)
  silkscreen extent -4.25,-4.25 4.25,4.25, body extent -4.25,-5.75 4.25,4.25, height 12.45
RTV0032A [mm] "QFN, 32-Leads, Body 5x5mm, Pitch 0.5mm"
  rrect40% 0.6x0.25 smd: 1(-2.4,1.75) 2(-2.4,1.25) 3(-2.4,0.75) 4(-2.4,0.25) 5(-2.4,-0.25) 6(-2.4,-0.75) 7(-2.4,-1.25) 8(-2.4,-1.75) 17(2.4,-1.75) 18(2.4,-1.25) 19(2.4,-0.75) 20(2.4,-0.25) 21(2.4,0.25) 22(2.4,0.75) 23(2.4,1.25) 24(2.4,1.75)
  rrect40% 0.25x0.6 smd: 9(-1.75,-2.4) 10(-1.25,-2.4) 11(-0.75,-2.4) 12(-0.25,-2.4) 13(0.25,-2.4) 14(0.75,-2.4) 15(1.25,-2.4) 16(1.75,-2.4) 25(1.75,2.4) 26(1.25,2.4) 27(0.75,2.4) 28(0.25,2.4) 29(-0.25,2.4) 30(-0.75,2.4) 31(-1.25,2.4) 32(-1.75,2.4)
  rrect3% 3.1x3.1 smd paste-1.55: 33(0,0)
  silkscreen extent -2.7,-2.7 2.7,2.7, body extent -2.55,-2.55 2.55,2.55, height 0.81

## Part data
C1: "CAP, CERM, 0.47 µF, 50 V, +/- 10%, X7R, 0603", Cap_Case=0603, Manufacturer=TDK, Supplier Part Number 1=445-5952-1-ND, TempCo=X7R, Tolerance_%=10, Value1="0.010974 ohm", Value2=50V, ValueDisplayed=0.47µF
C2: "CAP, CERM, 0.1 µF, 50 V, +/- 10%, X7R, AEC-Q200 Grade 1, 0402", Cap_Case=0402, Manufacturer=TDK, Supplier Part Number 1=445-6899-1-ND, TempCo=X7R, Tolerance_%=10, Value1=Unknown, Value2=50V, ValueDisplayed=0.1µF
C3 C12 C35 C38: "CAP, CERM, 1 µF, 10 V, +/- 10%, X5R, 0402", Cap_Case=0402, Manufacturer=MuRata, Supplier Part Number 1=490-3890-1-ND, TempCo=X5R, Tolerance_%=10, Value1=Unknown, Value2=10V, ValueDisplayed=1µF
C4 C19 C23 C25 C27 C28: "CAP, CERM, 0.1uF, 16V, +/-10%, X7R, 0402", Cap_Case=0402, Manufacturer=MuRata, Supplier Part Number 1=490-3261-1-ND, TempCo=X7R, Tolerance_%=10, Value1=Unknown, Value2=16V, ValueDisplayed=0.1µF
C5 C8 C11: "CAP, CERM, 10uF, 10V, +/-10%, X7R, 0805", Cap_Case=0805, Manufacturer=MuRata, Supplier Part Number 1=490-3905-1-ND, TempCo=X7R, Tolerance_%=10, Value1="0.003 ohm", Value2=10V, ValueDisplayed=10µF
C6 C9: "CAP, CERM, 0.1 µF, 16 V, +/- 10%, X7R, 0402", Cap_Case=0402, Manufacturer=MuRata, Supplier Part Number 1=490-4759-2-ND, TempCo=X7R, Tolerance_%=10, Value1=Unknown, Value2=16V, ValueDisplayed=0.1µF
C7 C10 C13 C16 C20 C24 C26 C29 C40: "CAP, CERM, 0.01uF, 16V, +/-10%, X7R, 0402", Cap_Case=0402, Manufacturer=MuRata, Supplier Part Number 1=490-1313-1-ND, TempCo=X7R, Tolerance_%=10, Value1=Unknown, Value2=16V, ValueDisplayed=0.01µF
C14: "CAP, CERM, 4.7 µF, 6.3 V, +/- 10%, X7R, 0603", Cap_Case=0603, Manufacturer="Taiyo Yuden", TempCo=X7R, Tolerance_%=10, Value1=Unknown, Value2=6.3V, ValueDisplayed=4.7µF
C15 C39: "CAP, CERM, 0.1 µF, 16 V, +/- 10%, X7R, 0402", Cap_Case=0402, Manufacturer=MuRata, Supplier Part Number 1=490-3261-1-ND, TempCo=X7R, Tolerance_%=10, Value1=Unknown, Value2=16V, ValueDisplayed=0.1µF
C17 C41: "CAP, CERM, 0.1 µF, 50 V, +/- 10%, X7R, AEC-Q200 Grade 1, 0402", Cap_Case=0402, Manufacturer=TDK, Supplier Part Number 1=445-6899-1-ND, TempCo=X7R, Tolerance_%=10, Value1="0.039064 ohm", Value2=50V, ValueDisplayed=0.1µF
C18 C22: library part Capacitor, "CAP CER 4.7UF 6.3V 10% X7R 0603", Alternate Manufacturer=-, Manufacturer="Samsung Electro-Mechanics America, Inc", Operating Temperature="-55°C ~ 125°C", Supplier Part Number 1=1276-2087-1-ND, TempCo=X7R, Tolerance_%=±10%
C21: "CAP, CERM, 0.047 µF, 50 V, +/- 10%, X7R, AEC-Q200 Grade 1, 0402", Cap_Case=0402, Manufacturer=TDK, Supplier Part Number 1=445-6897-1-ND, TempCo=X7R, Tolerance_%=10, Value1="0.06407 ohm", Value2=50V, ValueDisplayed=0.047µF
C30: "CAP, CERM, 10 µF, 50 V, +/- 10%, X5R, 1206_190", Cap_Case=1206, Manufacturer=TDK, Supplier Part Number 1=445-7886-1-ND, TempCo=X5R, Tolerance_%=10, Value1=Unknown, Value2=50V, ValueDisplayed=10µF
C31: "CAP, CERM, 22 µF, 6.3 V, +/- 20%, X7R, 0805", Cap_Case=0805, Manufacturer="Samsung Electro-Mechanics", TempCo=X7R, Tolerance_%=20, Value1=Unknown, Value2=6.3V, ValueDisplayed=22µF
C32: "CAP, CERM, 10 µF, 16 V, +/- 10%, X7R, 0805", Cap_Case=0805, Manufacturer="Samsung Electro-Mechanics", TempCo=X7R, Tolerance_%=10, Value1=Unknown, Value2=16V, ValueDisplayed=10µF
C33: "CAP, CERM, 10 µF, 10 V, +/- 10%, X7R, 0805", Cap_Case=0805, Manufacturer=MuRata, Supplier Part Number 1=490-3905-1-ND, TempCo=X7R, Tolerance_%=10, Value1="0.003 ohm", Value2=10V, ValueDisplayed=10µF
C34: "CAP, CERM, 4.7 µF, 50 V, +/- 20%, X5R, AEC-Q200 Grade 3, 0805", Cap_Case=0805, Manufacturer=MuRata, TempCo=X5R, Tolerance_%=20, Value1=Unknown, Value2=50V, ValueDisplayed=4.7µF
C36: library part C1005X7R1E103K, "CAP, CERM, 0.1uF, 25V, +/-10%, X7R, 0402", Manufacturer="TDK Corporation", Operating Temperature="-55°C ~ 125°C", Ratings=-, Supplier Part Number 1=445-7348-1-ND, TempCo=X7R, Tolerance_%=±10%
C37 C42: "CAP, CERM, 1 µF, 10 V, +/- 10%, X7R, 0603", Cap_Case=0603, Manufacturer="Taiyo Yuden", Supplier Part Number 1=587-3410-1-ND, TempCo=X7R, Tolerance_%=10, Value1=Unknown, Value2=10V, ValueDisplayed=1µF
FID1 FID2 FID3 FID4: "Fiducial mark.  There is nothing to buy or mount.", Manufacturer=N/A
J1: "Connector, HF, 50 Ohm, TH", Color=Waterblue, Manufacturer=Rosenberger
L1 L7 L8 L9: "Ferrite Bead, 1000 ohm @ 100 MHz, 0.35 A, 0402", Manufacturer=MuRata, Supplier Part Number 1=490-5442-1-ND, Value1="0.49 ohm", Value2=0.35A
L3: "Inductor, Wirewound, 4.7 µH, 1.01 A, 0.1 ohm, SMD", Manufacturer="Taiyo Yuden", Supplier Part Number 1=587-1624-1-ND, Value1="0.1 ohm", Value2=1.01A, ValueDisplayed=4.7µH
L4: "Inductor, Wirewound, 100 µH, 0.27 A, 1.4 ohm, SMD", Manufacturer="Taiyo Yuden", Supplier Part Number 1=587-1628-1-ND, Value1="1.4 ohm", Value2=0.27A, ValueDisplayed=100µH
L10: "Inductor, Wirewound, Ferrite, 4.7 µH, 0.76 A, 0.384 ohm, SMD", Manufacturer="Taiyo Yuden", Supplier Part Number 1=587-4295-1-ND, Value1="0.384 ohm", Value2=0.76A, ValueDisplayed=4.7µH
L11: "Inductor, Multilayer, Ferrite, 2.2 µH, 0.4 A, 0.16 ohm, AEC-Q200 Grade 1, SMD", Manufacturer=TDK, Supplier Part Number 1=445-17077-1-ND, Value1="0.16 ohm", Value2=0.4A, ValueDisplayed=2.2µH
LBL1: library part THT-14-423-10, "Thermal Transfer Printable Labels, 0.650\" W x 0.200\" H - 10,000 per roll", Alternate Manufacturer=-, Manufacturer=Brady, Supplier Part Number 1=2065596
Logo2: library part Pb-Free
Logo3: library part FCC_disclaimer, "FCC_disclaimer"
R1 R9: "RES, 2.00 k, 1%, 0.063 W, 0402", Manufacturer=Vishay-Dale, Power_W=0.063, Supplier Part Number 1=541-2.00KLCT-ND, TempCo="100 ppm/C", Tolerance_%=1, Value1=1%, Value2=0.063W, Value_Code=2k00, ValueDisplayed=2.00k
R2 R15 R16: "RES, 10k ohm, 5%, 0.063W, 0402", Manufacturer=Vishay-Dale, Power_W=0.063, Supplier Part Number 1=71-CRCW0402J-10K-E3, TempCo="200 ppm/C", Tolerance_%=5, Value1=5%, Value2=0.063W, Value_Code=10k0
R3 R6: "RES, 10 k, 5%, 0.063 W, 0402", Manufacturer=Vishay-Dale, Power_W=0.063, Supplier Part Number 1=541-10KJCT-ND, TempCo="200 ppm/C", Tolerance_%=5, Value1=5%, Value2=0.063W, Value_Code=10k0, ValueDisplayed=10k
R4 R5 R7 R8: "RES, 3.3 k, 5%, 0.063 W, 0402", Manufacturer=Vishay-Dale, Power_W=0.063, Supplier Part Number 1=541-3.3KJCT-ND, TempCo="200 ppm/C", Tolerance_%=5, Value1=5%, Value2=0.063W, Value_Code=3k30, ValueDisplayed=3.3k
R10: "RES, 1.00 k, 1%, 0.063 W, 0402", Manufacturer=Vishay-Dale, Power_W=0.063, Supplier Part Number 1=541-1.00KLCT-ND, TempCo="100 ppm/C", Tolerance_%=1, Value1=1%, Value2=0.063W, Value_Code=1k00, ValueDisplayed=1.00k
R12: "RES, 49.9 ohm, 1%, 0.063W, 0402", Manufacturer=Vishay-Dale, Power_W=0.063, Supplier Part Number 1=541-49.9LCT-ND, TempCo="100 ppm/C", Tolerance_%=1, Value1=1%, Value2=0.063W, Value_Code=49R9
R13: "RES, 33 ohm, 5%, 0.063W, 0402", Manufacturer=Vishay-Dale, Power_W=0.063, Supplier Part Number 1=541-33JCT-ND, TempCo="200 ppm/C", Tolerance_%=5, Value1=5%, Value2=0.063W, Value_Code=33R0
R17: "RES, 0 ohm, 5%, 0.063W, 0402", Manufacturer=Vishay-Dale, Power_W=0.063, Supplier Part Number 1=541-0.0JCT-ND, TempCo="200 ppm/C", Tolerance_%=5, Value1=5%, Value2=0.063W, Value_Code=0000
R18: "RES, 4.70 k, 1%, 0.063 W, 0402", Manufacturer="TE Connectivity", Power_W=0.063, Supplier Part Number 1=A121542CT-ND, TempCo="100 ppm/C", Tolerance_%=1, Value1=1%, Value2=0.063W, Value_Code=4k70, ValueDisplayed=4.70k
U1: "DS90UB913A-Q1/DS90UB914A-Q1 25 to 100 MHz 10/20-Bit FPD-Link III Serializer and Deserializer, RTV0032A", Alternate Manufacturer=None, Manufacturer="Texas Instruments"
U2: library part AS0140, "1MP+ISP Single Package Solution, BGA130", Manufacturer="ON Semiconductor"
U3: "Synchronous Buck Regulator for 650mA Space Constraint Applications, DSX0010A", Alternate Manufacturer="Texas Instruments"
U4: "Automotive 250-mA, Ultra-Low-Noise, Low-IQ LDO, DBV0005A (SOT-5)", Alternate Manufacturer="Texas Instruments"
U5: "2.25-MHz 600-mA STEP-DOWN CONVERTER, DRV0006A", Alternate Manufacturer="Texas Instruments"
Y1: "OSC, 48MHz, 1.8 to 3.3V, SMD", Frequency=48MHz, Frequency Stability=±10ppm, Manufacturer="Abracon Corporation", Supplier Part Number 1=535-11198-1-ND
ZZ1: library part AssemblyNoteLabel, Alternate Manufacturer=-
ZZ2 ZZ3 ZZ4: library part AssemblyNote, Alternate Manufacturer=-

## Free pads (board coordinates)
  round 62.99 hole 62.99 unplated: MT1(86.55,1364.13) MT2(950.73,1364.13)
  round 60 hole 280 unplated: ""(519.63,404.63)

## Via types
v1: diameter 14, hole 6, Layer 1 - Top Layer to Layer 6 - Bottom Layer, tented both sides, 103 vias
v2: diameter 19.68, hole 7.87, Layer 1 - Top Layer to Layer 6 - Bottom Layer, 10 vias
v3: diameter 20, hole 8, Layer 1 - Top Layer to Layer 6 - Bottom Layer, tented both sides, 6 vias
v4: diameter 20, hole 10, Layer 1 - Top Layer to Layer 6 - Bottom Layer, tented both sides, 4 vias
v5: diameter 19.68, hole 7.87, Layer 1 - Top Layer to Layer 6 - Bottom Layer, tented bottom, 1 vias

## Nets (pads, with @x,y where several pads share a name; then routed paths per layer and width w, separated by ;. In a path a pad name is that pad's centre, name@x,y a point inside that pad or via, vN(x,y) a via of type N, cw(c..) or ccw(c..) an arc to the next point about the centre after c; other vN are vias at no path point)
1V8: C8.1 C9.1 C10.1 C18.1 C19.1 C20.1 C25.1 C26.1 C33.1 L7.1 L8.1 L11.2 R6.2 R7.2 R8.2 R15.2 R16.2 U1.11 U1.28 U2.E3 U2.F3 U2.G3 U2.H3 U2.J3 U2.K3 U2.M4 U2.M5 U2.M7 U5.3 | length 795.2
  Layer 1 - Top Layer w10: C20.1@588,1600.5 647.78,1540.54 U1.11@663.67,1540.54 ; C20.1@588.45,1600.05 588.47,1597.5 C20.1@588.5,1594.09 ; v1(698,1681.2) R16.2@709.11,1681.2 ; U1.28@852.49,1501.16 v1(872.4,1501.2)
  Layer 4 - Power w10: 677.94,1687.2 708.94,1687.2 804.9,1591.24 804.9,1574
  Layer 4 - Power w16: 804.9,1568.7 v1(872.4,1501.2)
  Layer 6 - Bottom Layer w10: v1(438.5,1553.5) 438.5,1529.65 U2.M4@456.47,1511.67 U2.M5@483.25,1511.67 ; R6.2@623.31,1171 589.19,1171 R8.2@589.19,1131.5 613.5,1131.5 628,1117 v1(628,1093.5) ; v1@701.79,1684.99 R15.2@736.6,1684.99 ; C25.1@849.18,1459.45 849.18,1488.55 C26.1@849.48,1488.85
  Layer 6 - Bottom Layer w12: U2.M7@536.79,1511.67 551.5,1526.5 v1(551.5,1573.5)
  Layer 6 - Bottom Layer w14: C26.1@849.48,1488.85 861.83,1501.2 v1(872.4,1501.2)
  other v1: 624.5,1193 437,1305 311.5,1320 437,1364.5 337.7,1405.2 441,1449.5 586,1656.5
2V8: C5.1 C6.1 C7.1 C11.1 C12.1 C13.1 C27.1 C37.1 L9.1 R4.2 R5.2 U2.C10 U2.D10 U2.D11 U2.E11 U2.H10 U2.J10 U2.K10 U2.K12 U4.5 Y1.1 Y1.4 | length 227.5
  Layer 1 - Top Layer w10: R4.2@789.3,1721.39 v1(857.41,1721.39)
  Layer 4 - Power w10: 773.5,1418.7 785.2,1418.7 850.7,1484.2
  Layer 6 - Bottom Layer w10: U2.H10@613.5,1404.59 613.5,1454.53 U2.K10@617.1,1458.13
  other v1: 788,1179 811,1220 733.5,1227 623.9,1278.1 753.4,1338.8 621.4,1418.3
3V3: C16.1 C31.1 C32.1 C35.1 C36.1 C42.1 L10.2 R10.2 U2.M6 U3.4 U3.9 U4.1 U4.3 U5.2 U5.5 | length 1528.8
  Layer 1 - Top Layer w10: v1(256,1123) U3.9@272.38,1129.82 ; U3.4@382.62,1169.18 U3.4@386.12,1169.18 411.87,1169.18 C16.1@419.4,1176.72 ; C16.1@423,1169.82 v1(439,1186) ; U5.2@656.69,1038.3 v1@677.2,1038.3
  Layer 1 - Top Layer w14: v1(882.9,1046.01) U4.3@882.9,1080.77
  Layer 4 - Power w6: v1(256,1123) 256,1208.04 ; 258,1210.04 267.96,1220 336.5,1220 370.5,1186 v1(439,1186)
  Layer 4 - Power w10: 151.6,1153.54 151.6,1386.8 135.5,1402.96 135.5,1419.8 155.8,1440.1 155.8,1458.7 189.52,1492.41 189.52,1524.07 360.44,1694.98 534.5,1695 547.5,1682 v1(547.5,1651) ; 226,1093 v1(256,1123) v1@258,1125
  Layer 6 - Bottom Layer w10: U2.M6@510.02,1511.67 513.28,1514.94 513.28,1554.13 521.5,1562.35 521.5,1580.08 548.5,1607.08 547.5,1608.08 v1(547.5,1651) ; R10.2@517,1039.81 549.19,1039.81 v3(557,1032)
  other v1: 303,980.5 554.5,980 349,983 449,985 350.9,1025.4 677.5,1038
  other v3: 819,987.5 820,1047
3V3_NRST: R2.2 R10.1 U3.6 U5.4 | length 1810.8
  Layer 1 - Top Layer w10: U3.6@275,1191.49 v1(275,1203) ; v1(568.5,1080.5) 576,1080.5 579.91,1076.59 U5.4@579.91,1063.89
  Layer 3 - Signal w5: v1(275,1203) 293.5,1221.5 293.5,1374 308,1388.5 308,1632 396,1720 827.4,1720 842.8,1704.6 865.9,1704.6 874.3,1696.2 874.3,1687 ; v1(671.7,1631.2) 705.8,1665.3 853.1,1665.3 874.3,1686.5
  Layer 4 - Power w5: v1(275,1203) 275,1106.5 301,1080.5 v1(568.5,1080.5)
  Layer 6 - Bottom Layer w10: R10.1@517,1079.18 567.18,1079.18 v1(568.5,1080.5) ; v1(671.7,1631.2) 671.7,1632.09 R2.2@692.8,1653.19
"9V IN": C2.1 C30.1 C34.1 C41.1 L4.2 R9.1 U3.7 U3.8 | length 238.5
  Layer 1 - Top Layer w10: L4.2@298,1409.5 318.5,1430 345,1430 R9.1@362.08,1412.92
  Layer 1 - Top Layer w12: L4.2@289,1419.5 v4(289,1457) ; L4.2@291.5,1383.5 v4(311,1364)
  Layer 6 - Bottom Layer w12: C34.1@299.53,1420 299.5,1375.5 v4(311,1364)
  Layer 6 - Bottom Layer w18: C34.1@289,1423.97 v4(289,1457)
CAM_SCL: R5.1 U1.4 U2.B3 | length 1088.7
  Layer 1 - Top Layer w6: U1.4@767.84,1605.49 767.8,1629.1 811.4,1672.7 R5.1@819.1,1672.7
  Layer 1 - Top Layer w10: R5.1@827.6,1681.51 848.71,1681.51 v1(857.3,1690.1)
  Layer 3 - Signal w5: v1@418,1232.5 411.6,1226.1 370.4,1226.1 352.4,1244.1 352.4,1522.8 525.5,1696 711.6,1695.9 732.2,1675.3 810.7,1675.3 825.5,1690.1 v1(857.3,1690.1)
  Layer 6 - Bottom Layer w10: v1@418,1232.5 418.25,1232.5 U2.B3@429.7,1243.96 U2.B3@429.46,1243.96
  other v1: 418.5,1233
CAM_SDA: R4.1 U1.5 U2.C12 | length 2053.5
  Layer 1 - Top Layer w6: U1.5@748.16,1605.49 748.16,1640.46 R4.1@789.3,1681.6
  Layer 1 - Top Layer w10: R4.1@788.1,1682.51 797.1,1682.5 v1(805,1690.4)
  Layer 3 - Signal w5: v1(173.17,1238.07) 201.43,1238.07 258,1181.5 288.7,1181.5 338.9,1231.6 338.8,1380.2 319.5,1399.5 319.6,1505.6 522.2,1708.2 787.2,1708.2 v1(805,1690.4)
  Layer 6 - Bottom Layer w5: v1(173.17,1238.07) 409.24,1002 556.5,1002 574.54,984 613.5,984 649,1019.5 649,1043.5 685,1079.5 685.1,1256.3 U2.C12@670.65,1270.73
  Layer 6 - Bottom Layer w8: U2.C12@670.65,1270.73 U2.C12@672.6,1268.78 ; U2.C12@672.6,1268.13 U2.C12@672.6,1268.78 ; U2.C12@672.6,1269.13 U2.C12@672.6,1268.78
D0: U1.19 U2.E2 | length 470.8
  Layer 1 - Top Layer w10: U1.19@729,1417.04 v1(729,1435.5)
  Layer 3 - Signal w5: v1(413.5,1335) 542.5,1335 572.6,1304.9 692.5,1304.9 713.4,1325.8 713.4,1419.9 v1(729,1435.5)
  Layer 6 - Bottom Layer w10: U2.E2@402.93,1324.27 413.5,1334.84 v1(413.5,1335)
D1: U1.20 U2.M10 | length 605.1
  Layer 1 - Top Layer w10: v1(747.4,1393.6) U1.20@747.4,1415.75
  Layer 3 - Signal w5: v1(597.5,1560.5) 600,1563 728.4,1563 745.1,1579.7 769.6,1579.7 826.6,1522.7 826.6,1472.8 849.9,1449.6 849.9,1385.9 834,1370 771,1370 v1(747.4,1393.6)
  Layer 6 - Bottom Layer w10: v1(597.5,1560.5) 597.5,1531.28 U2.M10@617.1,1511.67
D2: U1.21 U2.L8 | length 378.6
  Layer 1 - Top Layer w10: U1.21@768.2,1416.87 v1(768.2,1435.7)
  Layer 3 - Signal w5: v1(531,1461) 542.5,1449.5 605.6,1449.5 649.1,1493 753.5,1493 778.4,1468.1 778.4,1445.9 v1(768.2,1435.7) v1@768.1,1435.6
  Layer 6 - Bottom Layer w10: v1(531,1461) 539.66,1461 U2.L8@563.56,1484.9
D3: U1.22 U2.E12 | length 805.9
  Layer 1 - Top Layer w10: U1.22@787.53,1416.51 787.53,1391.27 790.5,1388.3 v1(790.5,1387.2)
  Layer 6 - Bottom Layer w5: U2.E12@670.65,1324.27 705.3,1289.6 ; 705.3,1289.7 705.3,1109.4 712.7,1102 864.5,1102 896,1133.8 896,1337 883,1350 824.5,1350 809.9,1364.6 809.9,1380.9 803.6,1387.2 v1(790.5,1387.2)
D4: U1.23 U2.L10 | length 412.4
  Layer 1 - Top Layer w10: U1.23@807.21,1416.51 807.21,1405.69 v1(828,1384.9)
  Layer 3 - Signal w5: v1(605.5,1473.5) 661.8,1529.6 769,1529.6 779.5,1519.1 779.5,1482.7 811.7,1450.5 811.7,1419.11 828,1402.8 v1(828,1384.9)
  Layer 6 - Bottom Layer w10: v1(605.5,1473.5) 605.7,1473.5 U2.L10@617.1,1484.9
D5: U1.24 U2.L3 | length 527.2
  Layer 1 - Top Layer w10: U1.24@826.31,1417.1 v1(826.31,1434.29)
  Layer 3 - Signal w5: v1(441.5,1473) 475.56,1473 487.96,1485.4 596.1,1485.4 655,1544 774,1544 790.6,1527.4 790.6,1486.7 826.3,1451 v1(826.31,1434.29)
  Layer 6 - Bottom Layer w10: U2.L3@429.7,1484.9 429.7,1484.8 v1(441.5,1473)
D6: U1.26 U2.D2 | length 671
  Layer 1 - Top Layer w5: U1.26@859.1,1461.8 875.29,1445.61 v1(875.5,1432)
  Layer 3 - Signal w5: v1(392.5,1287) 459.3,1287 516,1230.5 665.5,1230.5 746.5,1311 804.5,1311 875.5,1382 v1(875.5,1432)
  Layer 6 - Bottom Layer w10: v1@392,1286.5 392,1286.57 U2.D2@402.93,1297.5
D7: U1.27 U2.M9 | length 544.2
  Layer 1 - Top Layer w5: U1.27@852.49,1481.47 870.33,1481.47 879.5,1472.3 v1(879.5,1463.6)
  Layer 3 - Signal w5: v1(576,1554.5) 576,1562.5 592.6,1579.1 603,1579.1 609.1,1573 721.4,1573 759.2,1610.8 831.9,1610.8 847.9,1594.9 847.84,1495.26 v1(879.5,1463.6)
  Layer 6 - Bottom Layer w10: v1(576,1554.5) 576,1526.01 U2.M9@590.33,1511.67
D8: U1.29 U2.D12 | length 896.6
  Layer 1 - Top Layer w5: U1.29@852.49,1520.84 877,1520.9 v1(891.3,1535.2)
  Layer 6 - Bottom Layer w5: U2.D12@670.65,1297.5 695.1,1273.1 695.15,1103.1 708.4,1089.8 870.3,1089.8 906.5,1126 906.4,1520.1 v1(891.3,1535.2)
D9: U1.30 U2.J2 | length 779.6
  Layer 1 - Top Layer w5: U1.30@852.49,1540.53 875.2,1540.8 891,1556.6 v1(891,1571.3)
  Layer 3 - Signal w5: v1(391.5,1443) 383,1451.5 383.2,1524.5 448.5,1589.5 610.5,1589.5 616,1584.3 714.5,1584.3 751.3,1621.1 818.7,1621.1 842.6,1645 861.6,1645 872.8,1633.9 872.8,1614.9 890.9,1596.8 ; v1(891,1571.3) 891,1596.8
  Layer 6 - Bottom Layer w10: v1(391.5,1443) 402.93,1432.03 U2.J2@402.93,1431.36
D10: U1.31 U2.H2 | length 828.3
  Layer 1 - Top Layer w5: U1.31@858.7,1559.8 891,1592.1 v1(891,1619.8)
  Layer 3 - Signal w5: v1(390,1417.5) 364.5,1443 364.5,1520.6 469,1625 535,1625 544.5,1615.5 697.1,1615.6 723.5,1641.9 744.1,1641.9 754.3,1631.7 812.3,1631.7 ; 812.4,1631.7 835.7,1655 873.1,1655 891,1637.1 v1(891,1619.8)
  Layer 6 - Bottom Layer w10: v1(390,1417.5) U2.H2@402.93,1404.59
D11: U1.32 U2.E1 | length 923.5
  Layer 1 - Top Layer w5: v1(833.3,1580.6) U1.32@852.49,1579.9
  Layer 6 - Bottom Layer w5: U2.E1@376.16,1324.27 361.7,1338.7 361.7,1404.7 348.5,1418 348.5,1535.5 532.5,1719.5 802,1719.5 830.4,1691.3 830.4,1583.5 v1(833.3,1580.6)
DOUTP_F: C17.1 J1.1 L1.1 | length 363.5
  Layer 1 - Top Layer w20: J1.1@240.99,1645.74 240.6,1646.13 311,1576 ; 315.5,1577.5 469.5,1577.5 547,1500
FRAME_SYNC: U1.16 U2.B8 | length 750.8
  Layer 1 - Top Layer w10: v1(630.5,1444.7) 633.09,1442.11 U1.16@663.67,1442.11
  Layer 3 - Signal w5: v1(564.2,1277.1) 521.3,1320 403.6,1320 396.44,1327.22 396.44,1338.62 407.8,1350 545.3,1350 580.3,1315 684.9,1315 696.9,1327 696.9,1402.7 654.9,1444.7 v1(630.5,1444.7)
  Layer 6 - Bottom Layer w10: U2.B8@563.56,1243.96 v1@563.56,1276.46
